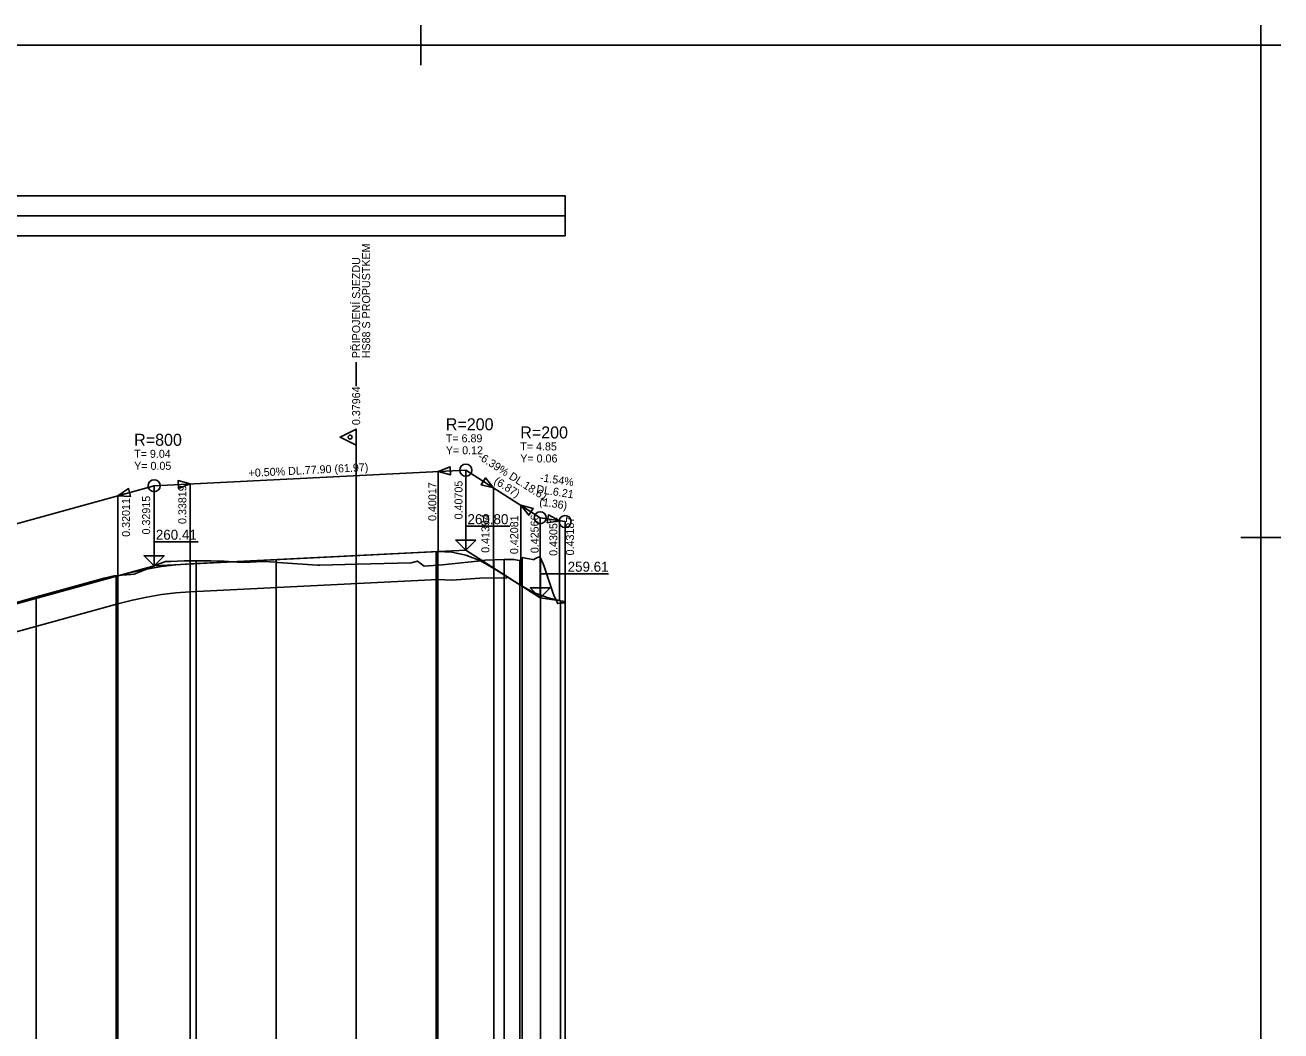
# Model space of a CAD drawing. Extents: x -5 to 681, y -26 to 404.
# Drawn here: x 366.9 to 680.8, y 152.9 to 404.3 of the extents above; entities that cross this region are included whole.
import ezdxf

# ---------------------------------------------------------------- set-up
doc = ezdxf.new("R2010")
doc.units = 0
for name, color, linetype in [('KOTA', 7, 'Continuous'), ('NOVY_STAV', 7, 'Continuous'), ('NS_OBLOUK', 7, 'Continuous'), ('POPISY_NAD_TERENEM', 7, 'Continuous'), ('PRIKOPY', 7, 'Continuous'), ('REZY_PO', 7, 'Continuous'), ('SVK_STAT', 7, 'Continuous'), ('TABULKY', 7, 'Continuous'), ('ZNACKY', 7, 'Continuous')]:
    doc.layers.add(name, color=color, linetype=linetype)

msp = doc.modelspace()

# ---------------------------------------------------------------- linework, layer by layer
for p, q in [((465.78, 404.27), (465.78, 394.27)), ((465.78, 404.27), (465.78, 394.27)), ((465.78, 404.27), (465.78, 394.27)), ((465.78, 404.27), (465.78, 394.27)), ((465.78, 404.27), (465.78, 394.27)), ((465.78, 404.27), (465.78, 394.27)), ((465.78, 404.27), (465.78, 394.27)), ((465.78, 404.27), (465.78, 394.27)), ((465.78, 404.27), (465.78, 394.27)), ((465.78, 404.27), (465.78, 394.27)), ((465.78, 404.27), (465.78, 394.27)), ((465.78, 404.27), (465.78, 394.27)), ((465.78, 404.27), (465.78, 394.27)), ((465.78, 404.27), (465.78, 394.27)), ((465.78, 404.27), (465.78, 394.27)), ((465.78, 404.27), (465.78, 394.27)), ((465.78, 404.27), (465.78, 394.27)), ((465.78, 404.27), (465.78, 394.27)), ((465.78, 404.27), (465.78, 394.27)), ((465.78, 404.27), (465.78, 394.27)), ((675.78, 404.23), (675.78, 394.23)), ((675.78, 404.23), (675.78, 394.23)), ((675.78, 404.23), (675.78, 394.23)), ((675.78, 404.23), (675.78, 394.23)), ((675.78, 404.23), (675.78, 394.23)), ((675.78, 404.23), (675.78, 394.23)), ((675.78, 404.23), (675.78, 394.23)), ((675.78, 404.23), (675.78, 394.23)), ((675.78, 404.23), (675.78, 394.23)), ((675.78, 404.23), (675.78, 394.23)), ((470.78, 399.27), (460.78, 399.27)), ((470.78, 399.27), (460.78, 399.27)), ((470.78, 399.27), (460.78, 399.27)), ((470.78, 399.27), (460.78, 399.27)), ((470.78, 399.27), (460.78, 399.27)), ((470.78, 399.27), (460.78, 399.27)), ((470.78, 399.27), (460.78, 399.27)), ((470.78, 399.27), (460.78, 399.27)), ((470.78, 399.27), (460.78, 399.27)), ((470.78, 399.27), (460.78, 399.27)), ((470.78, 399.27), (460.78, 399.27)), ((470.78, 399.27), (460.78, 399.27)), ((470.78, 399.27), (460.78, 399.27)), ((470.78, 399.27), (460.78, 399.27)), ((470.78, 399.27), (460.78, 399.27)), ((470.78, 399.27), (460.78, 399.27)), ((470.78, 399.27), (460.78, 399.27)), ((470.78, 399.27), (460.78, 399.27)), ((470.78, 399.27), (460.78, 399.27)), ((470.78, 399.27), (460.78, 399.27)), ((680.78, 399.23), (670.78, 399.23)), ((680.78, 399.23), (670.78, 399.23)), ((680.78, 399.23), (670.78, 399.23)), ((680.78, 399.23), (670.78, 399.23)), ((680.78, 399.23), (670.78, 399.23)), ((680.78, 399.23), (670.78, 399.23)), ((680.78, 399.23), (670.78, 399.23)), ((680.78, 399.23), (670.78, 399.23)), ((680.78, 399.23), (670.78, 399.23)), ((680.78, 399.23), (670.78, 399.23)), ((675.78, 281.23), (675.78, 271.23)), ((675.78, 281.23), (675.78, 271.23)), ((675.78, 281.23), (675.78, 271.23)), ((675.78, 281.23), (675.78, 271.23)), ((675.78, 281.23), (675.78, 271.23)), ((675.78, 281.23), (675.78, 271.23)), ((675.78, 281.23), (675.78, 271.23)), ((675.78, 281.23), (675.78, 271.23)), ((675.78, 281.23), (675.78, 271.23)), ((675.78, 281.23), (675.78, 271.23)), ((675.78, 281.23), (675.78, 271.23)), ((675.78, 281.23), (675.78, 271.23)), ((675.78, 281.23), (675.78, 271.23)), ((675.78, 281.23), (675.78, 271.23)), ((675.78, 281.23), (675.78, 271.23)), ((675.78, 281.23), (675.78, 271.23)), ((675.78, 281.23), (675.78, 271.23)), ((675.78, 281.23), (675.78, 271.23)), ((675.78, 281.23), (675.78, 271.23)), ((675.78, 281.23), (675.78, 271.23)), ((675.78, 281.23), (675.78, 271.23)), ((675.78, 281.23), (675.78, 271.23)), ((675.78, 281.23), (675.78, 271.23)), ((675.78, 281.23), (675.78, 271.23)), ((675.78, 281.23), (675.78, 271.23)), ((675.78, 281.23), (675.78, 271.23)), ((675.78, 281.23), (675.78, 271.23)), ((675.78, 281.23), (675.78, 271.23)), ((675.78, 281.23), (675.78, 271.23)), ((675.78, 281.23), (675.78, 271.23)), ((680.78, 276.23), (670.78, 276.23)), ((680.78, 276.23), (670.78, 276.23)), ((680.78, 276.23), (670.78, 276.23)), ((680.78, 276.23), (670.78, 276.23)), ((680.78, 276.23), (670.78, 276.23)), ((680.78, 276.23), (670.78, 276.23)), ((680.78, 276.23), (670.78, 276.23)), ((680.78, 276.23), (670.78, 276.23)), ((680.78, 276.23), (670.78, 276.23)), ((680.78, 276.23), (670.78, 276.23)), ((680.78, 276.23), (670.78, 276.23)), ((680.78, 276.23), (670.78, 276.23)), ((680.78, 276.23), (670.78, 276.23)), ((680.78, 276.23), (670.78, 276.23)), ((680.78, 276.23), (670.78, 276.23)), ((680.78, 276.23), (670.78, 276.23)), ((680.78, 276.23), (670.78, 276.23)), ((680.78, 276.23), (670.78, 276.23)), ((680.78, 276.23), (670.78, 276.23)), ((680.78, 276.23), (670.78, 276.23)), ((680.78, 276.23), (670.78, 276.23)), ((680.78, 276.23), (670.78, 276.23)), ((680.78, 276.23), (670.78, 276.23)), ((680.78, 276.23), (670.78, 276.23)), ((680.78, 276.23), (670.78, 276.23)), ((680.78, 276.23), (670.78, 276.23)), ((680.78, 276.23), (670.78, 276.23)), ((680.78, 276.23), (670.78, 276.23)), ((680.78, 276.23), (670.78, 276.23)), ((680.78, 276.23), (670.78, 276.23))]:
    msp.add_line(p, q)
msp.add_lwpolyline([(675.78, -20.77), (0.45, -20.77), (0.45, 399.23), (675.78, 399.23)], close=True)
at = {"layer": 'KOTA'}
for points in [[(477.05, 275.52), (474.55, 275.52), (477.05, 273.02), (477.05, 279.02), (488.05, 279.02)], [(399.15, 271.63), (396.65, 271.63), (399.15, 269.13), (399.15, 275.13), (410.15, 275.13)], [(477.05, 273.02), (477.05, 273.02), (479.55, 275.52), (477.05, 275.52)], [(399.15, 269.13), (399.15, 269.13), (401.65, 271.63), (399.15, 271.63)], [(495.66, 263.63), (493.16, 263.63), (495.66, 261.13), (495.66, 267.13), (512.69, 267.13)], [(495.66, 261.13), (495.66, 261.13), (498.16, 263.63), (495.66, 263.63)]]:
    msp.add_lwpolyline(points, dxfattribs=at)
at = {"layer": 'NOVY_STAV'}
for points in [[(399.15, 289.13), (477.05, 293.02)], [(477.05, 273.02), (477.05, 293.02)], [(477.05, 293.02), (495.66, 281.13)], [(288.85, 258.7), (399.15, 289.13)], [(399.15, 269.13), (399.15, 289.13)], [(495.66, 261.13), (495.66, 281.13)], [(495.66, 281.13), (501.87, 280.18)], [(501.87, 260.18), (501.87, 280.18)], [(70, 163.01), (130.33, 157.15), (250.75, 234.21), (288.85, 238.7), (399.15, 269.13), (477.05, 273.02), (495.66, 261.13), (501.87, 260.18)], [(295.17, 240.44), (390.11, 266.64), (393.73, 267.55), (397.34, 268.31), (400.96, 268.9), (404.58, 269.32), (408.19, 269.58), (470.04, 272.67), (473.55, 272.54), (477.05, 271.79), (480.56, 270.43), (484.07, 268.45), (490.55, 264.36), (493.96, 262.48), (497.42, 261.15), (500.74, 260.36), (501.87, 260.18)]]:
    msp.add_lwpolyline(points, dxfattribs=at)
for centre in [(477.05, 293.02), (399.15, 289.13), (495.66, 281.13), (501.87, 280.18)]:
    msp.add_circle(centre, 1.5, dxfattribs=at)
at = {"layer": 'NS_OBLOUK'}
for points in [[(470.17, 292.68), (473.12, 293.82), (473.21, 291.83), (470.17, 292.68)], [(470.17, 272.68), (470.17, 292.68)], [(408.19, 289.58), (405.15, 290.43), (405.25, 288.43), (408.19, 289.58)], [(408.19, 269.58), (408.19, 289.58)], [(483.94, 288.62), (481.95, 291.08), (480.87, 289.39), (483.94, 288.62)], [(390.11, 286.64), (392.74, 288.4), (393.27, 286.47), (390.11, 286.64)], [(390.11, 266.64), (390.11, 286.64)], [(483.94, 268.62), (483.94, 288.62)], [(490.81, 264.23), (490.81, 284.23)], [(490.81, 284.23), (493.88, 283.46), (492.8, 281.77), (490.81, 284.23)], [(500.51, 280.39), (497.7, 281.83), (497.39, 279.86), (500.51, 280.39)], [(500.51, 260.39), (500.51, 280.39)]]:
    msp.add_lwpolyline(points, dxfattribs=at)
at = {"layer": 'POPISY_NAD_TERENEM'}
msp.add_lwpolyline([(449.64, 314), (449.64, 320)], dxfattribs=at)
at = {"layer": 'PRIKOPY'}
msp.add_lwpolyline([(295.17, 233.44), (390.11, 259.64), (393.73, 260.55), (397.34, 261.31), (400.96, 261.9), (404.58, 262.32), (408.19, 262.58), (470.04, 265.67), (473.55, 265.54), (480.56, 266.02), (487.32, 266.1)], dxfattribs=at)
at = {"layer": 'REZY_PO'}
msp.add_lwpolyline([(360, 258.59), (370, 261.4), (377.02, 263.37), (378.51, 263.79), (380, 264.2), (383.33, 265.11), (386.67, 265.99), (389.12, 266.63), (390, 266.7), (393.33, 266.97), (394.17, 267.04), (396.67, 268.06), (400, 269.4), (401.95, 270.17), (403.33, 270.23), (406.67, 270.34), (409.24, 270.39), (410, 270.39), (413.33, 270.35), (415.63, 270.3), (416.67, 270.24), (420, 270.03), (421.74, 269.9), (423.18, 270), (426.36, 270.18), (426.54, 270.19), (429.54, 270), (430, 269.97), (440, 269.29), (440.59, 269.26), (450, 269.51), (460, 269.77), (463.36, 269.86), (464.94, 270.3), (466.6, 269.05), (470, 269.29), (471.15, 269.37), (480, 270.31), (481.88, 270.51), (486.6, 270.7), (487.45, 270.72), (488.3, 270.7), (489.15, 270.65), (490, 270.56), (490.89, 270.43), (490.96, 270.19), (490.98, 270.1), (491.19, 271.17), (491.92, 271.06), (492.88, 270.88), (493.84, 270.65), (493.89, 270.64), (494.8, 271.08), (495.61, 271.48), (495.76, 271.14), (496.55, 269.19), (498.79, 262.47), (499.02, 261.8), (499.13, 261.52), (499.13, 261.53), (499.2, 261.34), (499.74, 260.41), (500, 259.79), (500.05, 259.67), (501.04, 259.89), (501.87, 259.83)], dxfattribs=at)
at = {"layer": 'SVK_STAT'}
for points in [[(408.19, 98), (408.19, 270.37)], [(410.69, 98), (410.69, 99), (409.65, 101), (409.65, 270.39)], [(429.65, 98), (429.65, 270.65)], [(449.64, 98), (449.64, 271.65)], [(449.64, 98), (449.64, 271.65)], [(469.62, 98), (469.62, 272.65)], [(472.12, 98), (472.12, 99), (470.04, 101), (470.04, 272.67)], [(484.07, 98), (484.07, 270.6)], [(486.6, 98), (486.6, 270.7)], [(490.55, 98), (490.55, 270.48)], [(493.05, 98), (493.05, 99), (491.16, 101), (491.16, 271.02)], [(495.76, 98), (495.76, 271.14)], [(389.66, 98), (389.66, 266.68)], [(392.16, 98), (392.16, 99), (390.11, 101), (390.11, 266.71)], [(369.66, 98), (369.66, 261.3)], [(500.74, 98), (500.74, 260.36)], [(503.24, 98), (503.24, 99), (501.87, 101), (501.87, 260.18)]]:
    msp.add_lwpolyline(points, dxfattribs=at)
at = {"layer": 'TABULKY'}
for points in [[(70, 351.62), (501.87, 351.62), (501.87, 361.62), (70, 361.62), (70, 351.62)], [(70, 356.62), (501.87, 356.62)]]:
    msp.add_lwpolyline(points, dxfattribs=at)
at = {"layer": 'ZNACKY'}
msp.add_lwpolyline([(449.64, 271.65), (449.64, 303.28), (445.64, 301.28), (449.64, 299.28)], dxfattribs=at)
msp.add_circle((448.14, 301.28), 0.5, dxfattribs=at)

# ---------------------------------------------------------------- texts
at = {"layer": 'KOTA'}
for s, p in [('260.80', (477.47, 279.52)), ('260.41', (399.57, 275.63)), ('259.61', (502.51, 267.63))]:
    msp.add_text(s, height=2.5, dxfattribs=at).set_placement(p)
at = {"layer": 'NOVY_STAV'}
for s, rotation, p in [('-6.39% DL.18.61', 327.4341, (479.89, 295.95)), ('+0.50% DL.77.90 (61.97)', 2.8563, (422.8, 291.31)), ('-1.54%', 351.2617, (495.49, 290.28)), (' 0.40705', 90, (476.23, 279.98)), ('(6.87)', 327.4341, (483.89, 289.84)), ('DL.6.21', 351.2617, (494.59, 287.38)), (' 0.32915', 90, (398.15, 276.2)), ('(1.36)', 351.2617, (495.32, 284.23)), (' 0.42566', 90, (495.25, 271.53)), (' 0.43187', 90, (504.09, 270.98))]:
    msp.add_text(s, height=2, rotation=rotation, dxfattribs=at).set_placement(p)
at = {"layer": 'NS_OBLOUK'}
for s, height, p in [('R=200', 3, (472.05, 302.99)), ('R=800', 3, (394.15, 299.11)), ('T= 6.89', 2, (472.05, 299.99)), ('R=200', 3, (490.66, 300.95)), ('Y= 0.12', 2, (472.05, 296.99)), ('T= 4.85', 2, (490.66, 297.95)), ('T= 9.04', 2, (394.15, 296.11)), ('Y= 0.05', 2, (394.15, 293.11)), ('Y= 0.06', 2, (490.66, 294.95))]:
    msp.add_text(s, height=height, dxfattribs=at).set_placement(p)
for s, p in [(' 0.33819', (407.19, 278.82)), (' 0.40017', (469.68, 279.58)), (' 0.32011', (393.11, 275.62)), (' 0.41394', (482.94, 271.62)), (' 0.42081', (490.14, 271.3)), (' 0.43051', (499.93, 270.85))]:
    msp.add_text(s, height=2, rotation=90, dxfattribs=at).set_placement(p)
at = {"layer": 'POPISY_NAD_TERENEM'}
for s, p in [('HS88 S PROPUSTKEM', (453.14, 321)), ('PŘIPOJENÍ SJEZDU', (450.64, 321))]:
    msp.add_text(s, height=2, rotation=90, dxfattribs=at).set_placement(p)
at = {"layer": 'ZNACKY'}
msp.add_text('0.37964', height=2, rotation=90, dxfattribs=at).set_placement((450.64, 304.28))

doc.saveas('drawing.dxf')
